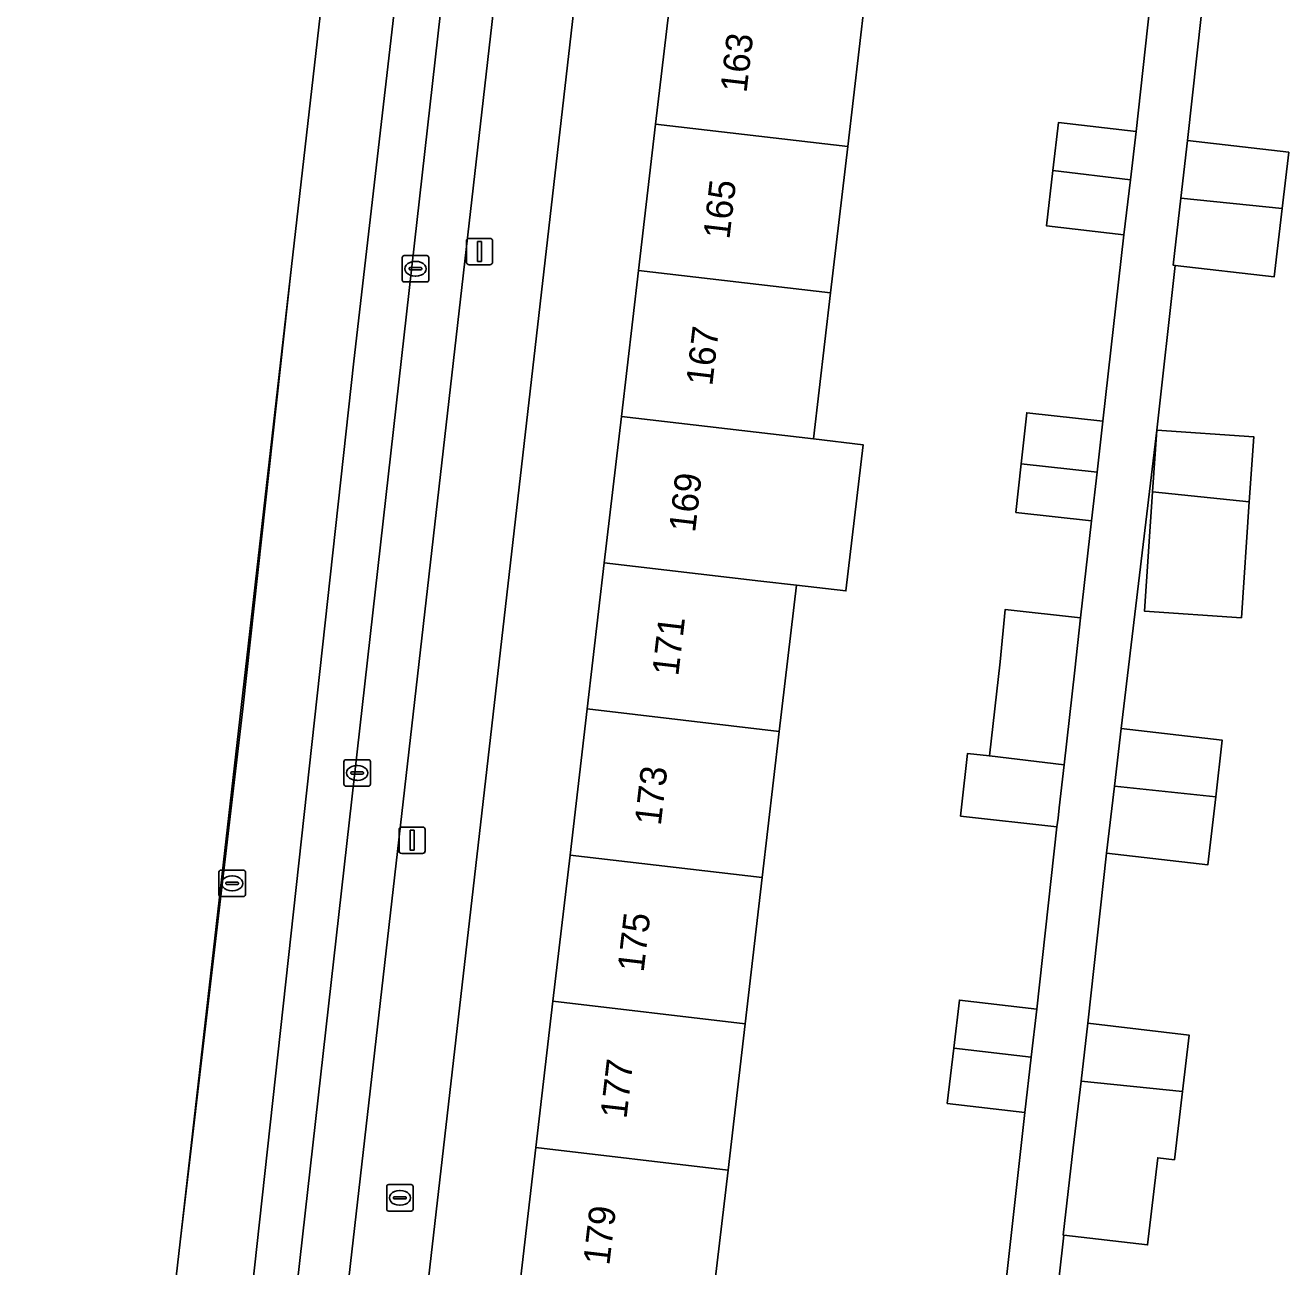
# Model space of a CAD drawing. Extents: x 162250 to 162661, y 380743 to 381606.
# Drawn here: x 162252.31 to 162300.12, y 380831.62 to 380878.59 of the extents above; entities that cross this region are included whole.
import ezdxf

# ---------------------------------------------------------------- set-up
doc = ezdxf.new("R2010")
doc.units = 0
for name, color, linetype in [('IMGEO_Brandkraan', 7, 'Continuous'), ('IMGEO_Erf', 7, 'Continuous'), ('IMGEO_Kolk', 7, 'Continuous'), ('IMGEO_Lichtmast', 7, 'Continuous'), ('IMGEO_Pand', 7, 'Continuous'), ('IMGEO_Pand_nummerreeks', 7, 'Continuous'), ('IMGEO_Parkeervlak_open', 7, 'Continuous'), ('IMGEO_Rijbaan_lokaal_gesloten', 7, 'Continuous'), ('IMGEO_Rioolput', 7, 'Continuous'), ('IMGEO_Voetpad_open', 7, 'Continuous')]:
    doc.layers.add(name, color=color, linetype=linetype)

msp = doc.modelspace()

# ---------------------------------------------------------------- linework, layer by layer
at = {"layer": 'IMGEO_Brandkraan'}
for p, q in [((162265.987, 380833.797), (162265.987, 380834.649)), ((162266.062, 380834.723), (162266.914, 380834.723)), ((162266.475, 380834.503), (162266.5, 380834.503)), ((162266.988, 380834.649), (162266.988, 380833.797)), ((162266.246, 380834.217), (162266.246, 380834.229)), ((162266.684, 380834.18), (162266.286, 380834.18)), ((162266.289, 380834.266), (162266.687, 380834.266)), ((162266.498, 380833.943), (162266.473, 380833.943)), ((162266.73, 380834.229), (162266.73, 380834.217)), ((162266.914, 380833.723), (162266.062, 380833.723))]:
    msp.add_line(p, q, dxfattribs=at)
for points in [[(162265.987, 380833.797), (162265.987, 380834.649)], [(162266.062, 380834.723), (162266.914, 380834.723)], [(162266.988, 380834.649), (162266.988, 380833.797)], [(162266.914, 380833.723), (162266.062, 380833.723)]]:
    msp.add_lwpolyline(points, dxfattribs=at)
for centre, radius, start, end in [((162266.064, 380834.647), 0.0765, 91.552, 178.448), ((162266.064, 380834.647), 0.0765, 91.552, 178.448), ((162266.912, 380834.647), 0.0765, 1.552, 88.448), ((162266.912, 380834.647), 0.0765, 1.552, 88.448), ((162266.286, 380834.226), 0.0403, 85.8775, 175.7526), ((162266.283, 380834.216), 0.0366, 178.938, 274.7102), ((162266.687, 380834.223), 0.043, 264.8664, 352.4533), ((162266.691, 380834.228), 0.0386, 1.7309, 96.639), ((162266.064, 380833.799), 0.0765, 181.552, 268.448), ((162266.064, 380833.799), 0.0765, 181.552, 268.448), ((162266.912, 380833.799), 0.0765, 271.552, 358.448), ((162266.912, 380833.799), 0.0765, 271.552, 358.448)]:
    msp.add_arc(centre, radius, start, end, dxfattribs=at)
for centre, major_axis, ratio, start_param, end_param in [((162266.474, 380834.223), (-0.387, 0.002), 0.722429, 4.712389, 7.853982), ((162266.499, 380834.223), (-0.39, 0.002), 0.717154, 1.570796, 4.712389)]:
    msp.add_ellipse(centre, major_axis=major_axis, ratio=ratio, start_param=start_param, end_param=end_param, dxfattribs=at)
at = {"layer": 'IMGEO_Erf'}
for points in [[(162269.042, 380813.997), (162269.69, 380819.53), (162270.337, 380825.062), (162270.984, 380830.594), (162271.631, 380836.125), (162272.279, 380841.658), (162272.926, 380847.19), (162273.573, 380852.722), (162274.22, 380858.254), (162274.867, 380863.786), (162275.515, 380869.318), (162276.162, 380874.85), (162276.809, 380880.382), (162277.456, 380885.915), (162278.103, 380891.447), (162278.751, 380896.979), (162279.391, 380902.457), (162275.776, 380902.864), (162265.001, 380808.699), (162268.381, 380808.343)], [(162295.125, 380863.27), (162298.793, 380863.019), (162298.624, 380860.554), (162298.324, 380856.175), (162294.657, 380856.426), (162294.965, 380860.931)]]:
    msp.add_lwpolyline(points, close=True, dxfattribs=at)
for points in [[(162289.337, 380830.294), (162290.131, 380837.454), (162287.199, 380837.797), (162287.443, 380839.886), (162287.656, 380841.708), (162290.589, 380841.365), (162291.349, 380848.255), (162287.699, 380848.667), (162287.738, 380849.006), (162287.967, 380851.038), (162288.794, 380850.942), (162289.197, 380854.51), (162289.387, 380856.481), (162292.244, 380856.167), (162292.659, 380859.845), (162289.792, 380860.161), (162289.994, 380861.997), (162290.207, 380863.931), (162293.085, 380863.613), (162293.882, 380870.66), (162290.95, 380871.003), (162291.194, 380873.092), (162291.407, 380874.914), (162294.34, 380874.571), (162295.132, 380881.73)], [(162296.997, 380880.656), (162296.291, 380874.233), (162300.117, 380873.786), (162299.869, 380871.663), (162299.565, 380869.07), (162295.825, 380869.507), (162295.125, 380863.27), (162293.778, 380851.983), (162297.604, 380851.536), (162297.354, 380849.399), (162297.052, 380846.82), (162293.226, 380847.267), (162292.518, 380840.827), (162296.344, 380840.38), (162296.094, 380838.244), (162295.792, 380835.664), (162295.159, 380835.738), (162294.774, 380832.44), (162291.602, 380832.81), (162291.255, 380829.657)], [(162284.078, 380879.532), (162283.431, 380874), (162282.784, 380868.469), (162282.137, 380862.937), (162284.009, 380862.718), (162283.362, 380857.185), (162281.49, 380857.404), (162280.842, 380851.872), (162280.195, 380846.34), (162279.548, 380840.808), (162278.901, 380835.275), (162278.254, 380829.744)]]:
    msp.add_lwpolyline(points, dxfattribs=at)
at = {"layer": 'IMGEO_Kolk'}
for p, q in [((162266.577, 380868.952), (162266.577, 380869.804)), ((162266.652, 380869.878), (162267.504, 380869.878)), ((162267.578, 380869.804), (162267.578, 380868.952)), ((162266.836, 380869.372), (162266.836, 380869.384)), ((162267.274, 380869.335), (162266.876, 380869.335)), ((162266.879, 380869.421), (162267.277, 380869.421)), ((162267.065, 380869.658), (162267.09, 380869.658)), ((162267.32, 380869.384), (162267.32, 380869.372)), ((162267.504, 380868.878), (162266.652, 380868.878)), ((162267.088, 380869.098), (162267.063, 380869.098)), ((162264.369, 380849.874), (162264.369, 380850.726)), ((162264.444, 380850.8), (162265.296, 380850.8)), ((162264.857, 380850.58), (162264.882, 380850.58)), ((162265.37, 380850.726), (162265.37, 380849.874)), ((162264.628, 380850.294), (162264.628, 380850.306)), ((162265.066, 380850.257), (162264.668, 380850.257)), ((162264.671, 380850.343), (162265.069, 380850.343)), ((162265.112, 380850.306), (162265.112, 380850.294)), ((162265.296, 380849.8), (162264.444, 380849.8)), ((162264.88, 380850.02), (162264.855, 380850.02))]:
    msp.add_line(p, q, dxfattribs=at)
for points in [[(162266.577, 380868.952), (162266.577, 380869.804)], [(162266.652, 380869.878), (162267.504, 380869.878)], [(162267.578, 380869.804), (162267.578, 380868.952)], [(162267.504, 380868.878), (162266.652, 380868.878)], [(162264.369, 380849.874), (162264.369, 380850.726)], [(162264.444, 380850.8), (162265.296, 380850.8)], [(162265.37, 380850.726), (162265.37, 380849.874)], [(162265.296, 380849.8), (162264.444, 380849.8)]]:
    msp.add_lwpolyline(points, dxfattribs=at)
for centre, radius, start, end in [((162266.654, 380869.802), 0.0765, 91.552, 178.448), ((162266.654, 380869.802), 0.0765, 91.552, 178.448), ((162267.502, 380869.802), 0.0765, 1.552, 88.448), ((162267.502, 380869.802), 0.0765, 1.552, 88.448), ((162266.876, 380869.381), 0.0403, 85.8775, 175.7526), ((162266.873, 380869.371), 0.0366, 178.938, 274.7102), ((162267.277, 380869.378), 0.043, 264.8664, 352.4533), ((162267.281, 380869.383), 0.0386, 1.7309, 96.639), ((162266.654, 380868.954), 0.0765, 181.552, 268.448), ((162266.654, 380868.954), 0.0765, 181.552, 268.448), ((162267.502, 380868.954), 0.0765, 271.552, 358.448), ((162267.502, 380868.954), 0.0765, 271.552, 358.448), ((162264.446, 380850.724), 0.0765, 91.552, 178.448), ((162264.446, 380850.724), 0.0765, 91.552, 178.448), ((162265.294, 380850.724), 0.0765, 1.552, 88.448), ((162265.294, 380850.724), 0.0765, 1.552, 88.448), ((162264.668, 380850.303), 0.0403, 85.8775, 175.7526), ((162264.665, 380850.293), 0.0366, 178.938, 274.7102), ((162265.069, 380850.3), 0.043, 264.8664, 352.4533), ((162265.073, 380850.305), 0.0386, 1.7309, 96.639), ((162264.446, 380849.876), 0.0765, 181.552, 268.448), ((162264.446, 380849.876), 0.0765, 181.552, 268.448), ((162265.294, 380849.876), 0.0765, 271.552, 358.448), ((162265.294, 380849.876), 0.0765, 271.552, 358.448)]:
    msp.add_arc(centre, radius, start, end, dxfattribs=at)
for centre, major_axis, ratio, start_param, end_param in [((162267.064, 380869.378), (-0.387, 0.002), 0.722429, 4.712389, 7.853982), ((162267.089, 380869.378), (-0.39, 0.002), 0.717154, 1.570796, 4.712389), ((162264.856, 380850.3), (-0.387, 0.002), 0.722429, 4.712389, 7.853982), ((162264.881, 380850.3), (-0.39, 0.002), 0.717154, 1.570796, 4.712389)]:
    msp.add_ellipse(centre, major_axis=major_axis, ratio=ratio, start_param=start_param, end_param=end_param, dxfattribs=at)
at = {"layer": 'IMGEO_Lichtmast'}
for p, q in [((162269.003, 380869.629), (162269.003, 380870.429)), ((162269.003, 380870.429), (162269.003, 380869.629)), ((162269.103, 380870.529), (162269.893, 380870.529)), ((162269.893, 380870.529), (162269.103, 380870.529)), ((162269.993, 380870.429), (162269.993, 380869.629)), ((162269.993, 380869.629), (162269.993, 380870.429)), ((162269.893, 380869.529), (162269.103, 380869.529)), ((162269.103, 380869.529), (162269.893, 380869.529)), ((162266.554, 380848.254), (162267.344, 380848.254)), ((162267.344, 380848.254), (162266.554, 380848.254)), ((162266.454, 380847.354), (162266.454, 380848.154)), ((162266.454, 380848.154), (162266.454, 380847.354)), ((162267.444, 380848.154), (162267.444, 380847.354)), ((162267.444, 380847.354), (162267.444, 380848.154)), ((162267.344, 380847.254), (162266.554, 380847.254)), ((162266.554, 380847.254), (162267.344, 380847.254))]:
    msp.add_line(p, q, dxfattribs=at)
for points in [[(162269.423, 380870.404), (162269.573, 380870.404), (162269.573, 380869.654), (162269.423, 380869.654), (162269.423, 380870.404)], [(162266.874, 380848.129), (162267.024, 380848.129), (162267.024, 380847.379), (162266.874, 380847.379), (162266.874, 380848.129)]]:
    msp.add_lwpolyline(points, dxfattribs=at)
for centre, start, end in [((162269.103, 380870.429), 90, 180), ((162269.103, 380870.429), 90, 180), ((162269.893, 380870.429), 0, 90), ((162269.893, 380870.429), 360, 90), ((162269.103, 380869.629), 180, 270), ((162269.103, 380869.629), 180, 270), ((162269.893, 380869.629), 270, 0), ((162269.893, 380869.629), 270, 0), ((162266.554, 380848.154), 90, 180), ((162266.554, 380848.154), 90, 180), ((162267.344, 380848.154), 0, 90), ((162267.344, 380848.154), 360, 90), ((162266.554, 380847.354), 180, 270), ((162266.554, 380847.354), 180, 270), ((162267.344, 380847.354), 270, 0), ((162267.344, 380847.354), 270, 0)]:
    msp.add_arc(centre, 0.1, start, end, dxfattribs=at)
at = {"layer": 'IMGEO_Pand'}
for points in [[(162283.431, 380874), (162284.078, 380879.532), (162276.809, 380880.382), (162276.162, 380874.85)], [(162283.431, 380874), (162276.162, 380874.85), (162275.515, 380869.318), (162282.784, 380868.469)], [(162294.127, 380872.749), (162294.34, 380874.571), (162291.407, 380874.914), (162291.194, 380873.092)], [(162296.035, 380872.047), (162299.869, 380871.663), (162300.117, 380873.786), (162296.291, 380874.233)], [(162294.127, 380872.749), (162291.194, 380873.092), (162290.95, 380871.003), (162293.882, 380870.66)], [(162299.869, 380871.663), (162296.035, 380872.047), (162295.739, 380869.517), (162295.825, 380869.507), (162299.565, 380869.07)], [(162275.515, 380869.318), (162274.867, 380863.786), (162282.137, 380862.937), (162282.784, 380868.469)], [(162282.137, 380862.937), (162274.867, 380863.786), (162274.22, 380858.254), (162280.147, 380857.561), (162281.49, 380857.404), (162283.362, 380857.185), (162284.009, 380862.718)], [(162293.085, 380863.613), (162290.207, 380863.931), (162289.994, 380861.997), (162292.867, 380861.68)], [(162294.965, 380860.931), (162298.624, 380860.554), (162298.793, 380863.019), (162295.125, 380863.27)], [(162292.867, 380861.68), (162289.994, 380861.997), (162289.792, 380860.161), (162292.659, 380859.845)], [(162294.965, 380860.931), (162294.657, 380856.426), (162298.324, 380856.175), (162298.624, 380860.554)], [(162281.49, 380857.404), (162280.147, 380857.561), (162274.22, 380858.254), (162273.573, 380852.722), (162280.842, 380851.872)], [(162292.244, 380856.167), (162289.387, 380856.481), (162289.197, 380854.51), (162288.794, 380850.942), (162291.616, 380850.613), (162292.02, 380854.19)], [(162273.573, 380852.722), (162272.926, 380847.19), (162280.195, 380846.34), (162280.842, 380851.872)], [(162293.522, 380849.794), (162297.354, 380849.399), (162297.604, 380851.536), (162293.778, 380851.983)], [(162291.616, 380850.613), (162288.794, 380850.942), (162287.967, 380851.038), (162287.738, 380849.006), (162287.699, 380848.667), (162291.349, 380848.255), (162291.388, 380848.595), (162291.431, 380848.982)], [(162293.522, 380849.794), (162293.226, 380847.267), (162297.052, 380846.82), (162297.354, 380849.399)], [(162279.548, 380840.808), (162280.195, 380846.34), (162272.926, 380847.19), (162272.279, 380841.658)], [(162279.548, 380840.808), (162272.279, 380841.658), (162271.631, 380836.125), (162278.901, 380835.275)], [(162287.443, 380839.886), (162290.376, 380839.543), (162290.589, 380841.365), (162287.656, 380841.708)], [(162292.262, 380838.638), (162296.094, 380838.244), (162296.344, 380840.38), (162292.518, 380840.827)], [(162287.443, 380839.886), (162287.199, 380837.797), (162290.131, 380837.454), (162290.376, 380839.543)], [(162296.094, 380838.244), (162292.262, 380838.638), (162291.966, 380836.111), (162291.581, 380832.813), (162291.602, 380832.81), (162294.774, 380832.44), (162295.159, 380835.738), (162295.792, 380835.664)], [(162278.254, 380829.744), (162278.901, 380835.275), (162271.631, 380836.125), (162270.984, 380830.594)]]:
    msp.add_lwpolyline(points, close=True, dxfattribs=at)
at = {"layer": 'IMGEO_Parkeervlak_open'}
for points in [[(162268.906, 380886.915), (162261.715, 380823.119)], [(162263.962, 380825.98), (162270.453, 380882.943)]]:
    msp.add_lwpolyline(points, dxfattribs=at)
at = {"layer": 'IMGEO_Rijbaan_lokaal_gesloten'}
for points in [[(162252.312, 380781.239), (162257.154, 380780.607), (162257.633, 380784.935), (162258.149, 380794.31), (162258.723, 380801.22), (162259.12, 380806.851), (162260.905, 380806.961), (162259.96, 380812.232), (162259.402, 380817.069), (162264.75, 380865.883), (162268.297, 380896.697), (162270.009, 380896.53), (162270.161, 380897.858), (162265.681, 380898.298), (162265.681, 380898.298), (162262.388, 380869.467), (162260.545, 380852.722), (162258.173, 380832.558), (162252.312, 380781.239)], [(162268.906, 380886.915), (162269.304, 380890.388), (162270.009, 380896.53), (162268.297, 380896.697), (162264.75, 380865.883), (162259.402, 380817.069), (162259.96, 380812.232), (162260.905, 380806.961), (162262.487, 380808.761)], [(162261.397, 380820.291), (162261.715, 380823.119), (162268.906, 380886.915)]]:
    msp.add_lwpolyline(points, dxfattribs=at)
msp.add_lwpolyline([(162262.388, 380869.467), (162258.173, 380832.558), (162260.545, 380852.722)], close=True, dxfattribs=at)
at = {"layer": 'IMGEO_Rioolput'}
for p, q in [((162259.64, 380845.697), (162259.64, 380846.549)), ((162259.715, 380846.623), (162260.567, 380846.623)), ((162260.128, 380846.403), (162260.153, 380846.403)), ((162260.641, 380846.549), (162260.641, 380845.697)), ((162259.899, 380846.117), (162259.899, 380846.129)), ((162260.337, 380846.08), (162259.939, 380846.08)), ((162259.942, 380846.166), (162260.34, 380846.166)), ((162260.151, 380845.843), (162260.126, 380845.843)), ((162260.383, 380846.129), (162260.383, 380846.117)), ((162260.567, 380845.623), (162259.715, 380845.623))]:
    msp.add_line(p, q, dxfattribs=at)
for points in [[(162259.64, 380845.697), (162259.64, 380846.549)], [(162259.715, 380846.623), (162260.567, 380846.623)], [(162260.641, 380846.549), (162260.641, 380845.697)], [(162260.567, 380845.623), (162259.715, 380845.623)]]:
    msp.add_lwpolyline(points, dxfattribs=at)
for centre, radius, start, end in [((162259.717, 380846.547), 0.0765, 91.552, 178.448), ((162259.717, 380846.547), 0.0765, 91.552, 178.448), ((162260.565, 380846.547), 0.0765, 1.552, 88.448), ((162260.565, 380846.547), 0.0765, 1.552, 88.448), ((162259.939, 380846.126), 0.0403, 85.8775, 175.7526), ((162259.936, 380846.116), 0.0366, 178.938, 274.7102), ((162260.34, 380846.123), 0.043, 264.8664, 352.4533), ((162260.344, 380846.128), 0.0386, 1.7309, 96.639), ((162259.717, 380845.699), 0.0765, 181.552, 268.448), ((162259.717, 380845.699), 0.0765, 181.552, 268.448), ((162260.565, 380845.699), 0.0765, 271.552, 358.448), ((162260.565, 380845.699), 0.0765, 271.552, 358.448)]:
    msp.add_arc(centre, radius, start, end, dxfattribs=at)
for centre, major_axis, ratio, start_param, end_param in [((162260.127, 380846.123), (-0.387, 0.002), 0.722429, 4.712389, 7.853982), ((162260.152, 380846.123), (-0.39, 0.002), 0.717154, 1.570796, 4.712389)]:
    msp.add_ellipse(centre, major_axis=major_axis, ratio=ratio, start_param=start_param, end_param=end_param, dxfattribs=at)
at = {"layer": 'IMGEO_Voetpad_open'}
for points in [[(162268.495, 380808.33), (162268.381, 380808.343), (162265.001, 380808.699), (162275.776, 380902.864), (162276.17, 380906.721)], [(162270.687, 380901.451), (162270.161, 380897.858), (162270.009, 380896.53), (162269.304, 380890.388), (162272.281, 380890.119), (162271.517, 380882.847), (162270.453, 380882.943), (162263.962, 380825.98)], [(162295.132, 380881.73), (162294.34, 380874.571), (162294.127, 380872.749), (162293.882, 380870.66), (162293.085, 380863.613), (162292.867, 380861.68), (162292.659, 380859.845), (162292.244, 380856.167), (162292.02, 380854.19), (162291.616, 380850.613), (162291.431, 380848.982), (162291.388, 380848.595), (162291.349, 380848.255), (162290.589, 380841.365), (162290.376, 380839.543), (162290.131, 380837.454), (162289.337, 380830.294)], [(162288.303, 380805.578), (162288.712, 380808.256), (162288.954, 380810.669), (162290.703, 380824.941), (162290.999, 380827.471), (162291.255, 380829.657), (162291.602, 380832.81), (162291.581, 380832.813), (162291.966, 380836.111), (162292.262, 380838.638), (162292.518, 380840.827), (162293.226, 380847.267), (162293.522, 380849.794), (162293.778, 380851.983), (162295.125, 380863.27), (162295.825, 380869.507), (162295.739, 380869.517), (162296.035, 380872.047), (162296.291, 380874.233), (162296.997, 380880.656)]]:
    msp.add_lwpolyline(points, dxfattribs=at)

# ---------------------------------------------------------------- texts
at = {"layer": 'IMGEO_Pand_nummerreeks'}
for s, rotation, p in [('163', 83.3272, (162279.6, 380876.013)), ('165', 83.3272, (162278.952, 380870.467)), ('167', 83.3272, (162278.303, 380864.92)), ('169', 83.3253, (162277.654, 380859.374)), ('171', 83.3253, (162277.018, 380853.942)), ('173', 83.3272, (162276.356, 380848.281)), ('175', 83.3272, (162275.707, 380842.735)), ('177', 83.3272, (162275.058, 380837.188)), ('179', 83.3272, (162274.409, 380831.642))]:
    msp.add_text(s, height=1, rotation=rotation, dxfattribs=at).set_placement(p)

doc.saveas('drawing.dxf')
